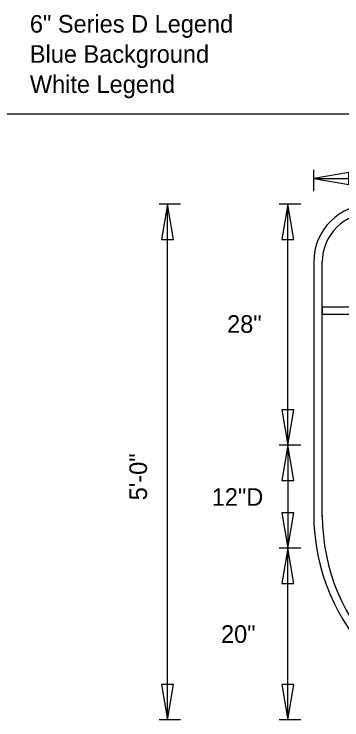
# Model space of a CAD drawing. Extents: x 0 to 770, y 0 to 495.
# Drawn here: x 195.7 to 260.9, y 209.5 to 349.8 of the extents above; entities that cross this region are included whole.
import ezdxf

# ---------------------------------------------------------------- set-up
doc = ezdxf.new("R2010")
doc.units = 0
for name, color, linetype in [('Dimension', 7, 'Continuous'), ('GSBWFill', 7, 'Continuous'), ('GSColorFill', 7, 'Continuous'), ('GSDims', 7, 'Continuous'), ('GSOutline', 7, 'Continuous'), ('IndexDetail_0', 7, 'Continuous'), ('SheetLines_dp', 7, 'Continuous'), ('TextStructures', 7, 'Continuous')]:
    doc.layers.add(name, color=color, linetype=linetype)

msp = doc.modelspace()

# ---------------------------------------------------------------- linework, layer by layer
at = {"layer": 'Dimension'}
for points in [[(255.25, 317.14), (262.27, 315.95), (262.27, 318.33)], [(226.2, 312.02), (225.01, 305), (227.39, 305)], [(250.12, 312.02), (248.94, 305), (251.31, 305)], [(250.12, 264.11), (251.31, 271.12), (248.94, 271.12)], [(250.12, 264.11), (248.94, 257.09), (251.31, 257.09)], [(250.12, 243.6), (251.31, 250.62), (248.94, 250.62)], [(250.12, 243.6), (248.94, 236.58), (251.31, 236.58)], [(226.2, 209.48), (227.39, 216.5), (225.01, 216.5)], [(250.12, 209.48), (251.31, 216.5), (248.94, 216.5)]]:
    msp.add_lwpolyline(points, close=True, dxfattribs=at)
at = {"layer": 'GSBWFill'}
for p, q in [((255.25, 300.48), (255.25, 250.5)), ((256.96, 249.87), (256.96, 300.48)), ((335.57, 291.51), (256.96, 291.51)), ((256.96, 291.51), (256.96, 290.14)), ((256.96, 290.14), (335.57, 290.14))]:
    msp.add_line(p, q, dxfattribs=at)
for radius in [11.53, 9.83]:
    msp.add_arc((266.79, 300.48), radius, 90, 180, dxfattribs=at)
at = {"layer": 'GSColorFill'}
for p, q in [((335.57, 291.51), (256.96, 291.51)), ((256.96, 291.51), (256.96, 290.14)), ((256.96, 290.14), (335.57, 290.14))]:
    msp.add_line(p, q, dxfattribs=at)
at = {"layer": 'GSDims'}
for p, q in [((255.25, 314.58), (255.25, 318.85)), ((255.25, 317.14), (337.28, 317.14)), ((228.76, 312.02), (224.49, 312.02)), ((226.2, 209.48), (226.2, 312.02)), ((252.69, 312.02), (248.41, 312.02)), ((250.12, 264.11), (250.12, 312.02)), ((252.69, 264.11), (248.41, 264.11)), ((252.69, 264.11), (248.41, 264.11)), ((250.12, 264.11), (250.12, 243.6)), ((252.69, 243.6), (248.41, 243.6)), ((252.69, 243.6), (248.41, 243.6)), ((250.12, 209.48), (250.12, 243.6)), ((228.76, 209.48), (224.49, 209.48)), ((252.69, 209.48), (248.41, 209.48))]:
    msp.add_line(p, q, dxfattribs=at)
at = {"layer": 'GSOutline'}
for p, q in [((335.57, 291.51), (256.96, 291.51)), ((256.96, 291.51), (256.96, 290.14)), ((256.96, 290.14), (335.57, 290.14))]:
    msp.add_line(p, q, dxfattribs=at)
at = {"layer": 'IndexDetail_0'}
for centre, radius, end in [((296.26, 250.5), 41.01, 360), ((296.27, 250.06), 39.3, 0)]:
    msp.add_arc(centre, radius, 180, end, dxfattribs=at)
at = {"layer": 'SheetLines_dp'}
msp.add_line((0, 330), (770, 330), dxfattribs=at)

# ---------------------------------------------------------------- texts
at = {"layer": 'TextStructures'}
for s, p in [('6" Series D Legend', (198.8, 346.12)), ('Blue Background', (198.8, 340.12)), ('White Legend  ', (198.8, 334.12)), ('28"', (238.03, 286.44)), ('12"D', (234.98, 252.05)), ('20"', (236.82, 224.8))]:
    msp.add_text(s, height=3.5, dxfattribs=at).set_placement(p)
msp.add_text('5\'-0"', height=3.5, rotation=90, dxfattribs=at).set_placement((222.1, 253.14))

doc.saveas('drawing.dxf')
